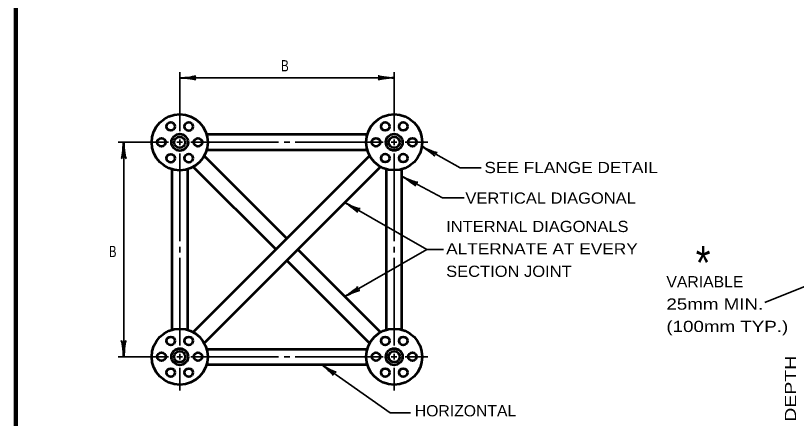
# Model space of a CAD drawing. Extents: x -29 to 827, y -14 to 530.
# Drawn here: x 28.3 to 196.8, y 249.5 to 336.4 of the extents above; entities that cross this region are included whole.
import ezdxf

# ---------------------------------------------------------------- set-up
doc = ezdxf.new("R2010")
doc.units = 0
doc.header["$LTSCALE"] = 0.97
doc.layers.add('1', color=7, linetype='Continuous', lineweight=53)

msp = doc.modelspace()

# ---------------------------------------------------------------- linework, layer by layer
at = {"layer": '1', "lineweight": 35}
for p, q in [((63.7556, 324.1479), (63.7556, 311.4169)), ((110.0276, 324.1479), (110.0276, 311.4279)), ((63.7556, 322.9239), (110.0276, 322.9239)), ((50.4356, 309.0279), (61.3488, 309.0279)), ((51.6596, 309.0279), (51.6596, 262.7559)), ((63.1556, 309.0279), (64.3556, 309.0279)), ((63.7556, 309.6279), (63.7556, 308.4039)), ((66.1488, 309.0279), (69.8036, 309.0279)), ((69.8036, 309.0279), (85.0676, 309.0279)), ((86.2676, 309.0279), (87.4916, 309.0279)), ((88.6916, 309.0279), (103.9796, 309.0279)), ((103.9796, 309.0279), (107.6276, 309.0279)), ((112.4276, 309.0279), (117.2756, 309.0279)), ((63.7556, 306.6169), (63.7556, 302.9799)), ((110.0276, 306.6279), (110.0276, 302.9799)), ((63.7556, 287.6919), (63.7556, 302.9799)), ((110.0276, 302.9799), (110.0276, 287.6919)), ((63.7556, 285.2679), (63.7556, 286.4919)), ((110.0276, 286.4919), (110.0276, 285.2679)), ((117.0596, 285.8919), (120.6836, 285.8919)), ((63.7556, 268.8039), (63.7556, 284.0679)), ((110.0276, 284.0679), (110.0276, 268.8039)), ((207.7316, 281.5678), (190.0196, 274.4878)), ((63.7556, 268.8039), (63.7556, 265.1559)), ((110.0276, 268.8039), (110.0276, 265.1559)), ((50.4356, 262.7559), (61.3556, 262.7559)), ((66.1556, 262.7559), (69.8036, 262.7559)), ((69.8036, 262.7559), (85.0676, 262.7559)), ((86.2676, 262.7559), (87.4916, 262.7559)), ((88.6916, 262.7559), (103.9796, 262.7559)), ((103.9796, 262.7559), (107.6276, 262.7559)), ((112.4276, 262.7559), (117.2756, 262.7559)), ((63.7556, 260.3559), (63.7556, 255.4839)), ((110.0276, 260.3559), (110.0276, 255.4839))]:
    msp.add_line(p, q, dxfattribs=at)
at = {"layer": '1'}
for p, q in [((104.1956, 310.6839), (69.5636, 310.6839)), ((104.1956, 307.3479), (69.5636, 307.3479)), ((104.7236, 306.0759), (66.6836, 268.0359)), ((69.0356, 306.0759), (86.8916, 288.2439)), ((66.6836, 303.7239), (84.5396, 285.8919)), ((107.0756, 303.7239), (69.0356, 265.6839)), ((62.0756, 303.1959), (62.0756, 268.5639)), ((65.4116, 303.1959), (65.4116, 268.5639)), ((108.3476, 268.5639), (108.3476, 303.1959)), ((111.6836, 268.5639), (111.6836, 303.1959)), ((89.2436, 285.8919), (107.0756, 268.0359)), ((86.8916, 283.5399), (104.7236, 265.6839)), ((69.5636, 264.4119), (104.1956, 264.4119)), ((69.5636, 261.0759), (104.1956, 261.0759))]:
    msp.add_line(p, q, dxfattribs=at)
at = {"layer": '1', "lineweight": 158}
msp.add_lwpolyline([(820.0407, 523.2545), (28.3407, 523.1545), (28.4407, -2.8455)], dxfattribs=at)
at = {"layer": '1', "lineweight": 35}
for points in [[(109.4036, 309.0279), (110.0276, 309.0279), (110.6276, 309.0279)], [(110.0276, 309.6279), (110.0276, 309.0279), (110.0276, 308.4039)], [(116.0276, 308.1399), (124.2836, 303.4839), (128.8196, 303.4839)], [(111.8276, 301.6119), (120.4436, 297.0279), (125.1236, 297.0279)], [(99.3716, 296.0199), (117.0596, 285.8919), (99.3716, 275.7399)], [(63.7556, 263.3559), (63.7556, 262.7559), (63.7556, 262.1559)], [(110.0276, 263.3559), (110.0276, 262.7559), (110.0276, 262.1559)], [(63.1556, 262.7559), (63.7556, 262.7559), (64.3556, 262.7559)], [(109.4036, 262.7559), (110.0276, 262.7559), (110.6276, 262.7559)], [(94.3316, 261.0759), (109.1396, 250.6839), (113.5556, 250.6839)]]:
    msp.add_lwpolyline(points, dxfattribs=at)
at = {"layer": '1'}
for centre, radius in [((63.7488, 309.0169), 6.048), ((110.0276, 309.0279), 6.048), ((108.0844, 312.4522), 0.9), ((111.9844, 312.4444), 0.9), ((61.8056, 312.4412), 0.9), ((65.7056, 312.4334), 0.9), ((63.7488, 309.0169), 1.8), ((63.7488, 309.0169), 1.2), ((110.0276, 309.0279), 1.8), ((110.0276, 309.0279), 1.2), ((59.8116, 309.0279), 0.9), ((67.686, 309.0279), 0.9), ((106.0904, 309.0389), 0.9), ((113.9648, 309.0389), 0.9), ((61.8056, 305.5926), 0.9), ((65.7056, 305.6004), 0.9), ((108.0844, 305.6036), 0.9), ((111.9844, 305.6114), 0.9), ((63.7556, 262.7559), 6.048), ((110.0276, 262.7559), 6.048), ((61.8124, 266.1802), 0.9), ((65.7124, 266.1724), 0.9), ((108.0844, 266.1802), 0.9), ((111.9844, 266.1724), 0.9), ((63.7556, 262.7559), 1.8), ((110.0276, 262.7559), 1.8), ((59.8184, 262.7669), 0.9), ((63.7556, 262.7559), 1.2), ((67.6928, 262.7669), 0.9), ((106.0904, 262.7669), 0.9), ((110.0276, 262.7559), 1.2), ((113.9648, 262.7669), 0.9), ((61.8124, 259.3316), 0.9), ((65.7124, 259.3394), 0.9), ((108.0844, 259.3316), 0.9), ((111.9844, 259.3394), 0.9)]:
    msp.add_circle(centre, radius, dxfattribs=at)
at = {"layer": '1', "lineweight": 40}
for centre, major_axis, ratio, start_param, end_param in [((65.1042, 322.6714), (-2.1246, 0.2125), 0.07063, 3.14071475, 5.41810995), ((65.1042, 322.6714), (-2.1246, 0.2125), 0.07063, 3.14071475, 5.41810995), ((65.0687, 323.2615), (-2.16, -0.1889), 0.122415, 0.89635335, 3.14159265), ((65.0687, 323.2615), (-2.16, -0.1889), 0.122415, 0.89635335, 3.14159265), ((108.6961, 322.5931), (2.16, 0.1889), 0.122415, 0.89635335, 3.14159265), ((108.6961, 322.5931), (2.16, 0.1889), 0.122415, 0.89635335, 3.14159265), ((108.6606, 323.1833), (2.1246, -0.2125), 0.07063, 3.14071475, 5.41810995), ((108.6606, 323.1833), (2.1246, -0.2125), 0.07063, 3.14071475, 5.41810995), ((51.3968, 307.6616), (0.2125, 2.1246), 0.07063, 3.14071475, 5.41810995), ((51.3968, 307.6616), (0.2125, 2.1246), 0.07063, 3.14071475, 5.41810995), ((51.987, 307.697), (-0.1889, 2.16), 0.122415, 0.89635335, 3.14159265), ((51.987, 307.697), (-0.1889, 2.16), 0.122415, 0.89635335, 3.14159265), ((117.0906, 307.2522), (-1.7435, 1.2325), 0.07063, 3.14071475, 5.41810995), ((117.0906, 307.2522), (-1.7435, 1.2325), 0.07063, 3.14071475, 5.41810995), ((117.3508, 307.783), (-1.9722, 0.9008), 0.122415, 0.89635335, 3.14159265), ((117.3508, 307.783), (-1.9722, 0.9008), 0.122415, 0.89635335, 3.14159265), ((112.9021, 300.7546), (1.7745, -1.1875), 0.07063, 6.28230741, 8.55970261), ((113.1486, 301.292), (-1.9946, 0.8501), 0.122415, 0.89635335, 3.14159265), ((100.4304, 295.1344), (1.7367, -1.2422), 0.07063, 6.28230741, 8.55970261), ((100.6936, 295.6638), (-1.9672, 0.9118), 0.122415, 0.89635335, 3.14159265), ((100.3607, 276.6824), (-1.7791, -1.2394), 0.122415, 0.89635335, 3.14159265), ((100.6853, 276.1882), (-1.9483, -0.8737), 0.07063, 3.14071475, 5.41810995), ((51.3186, 264.0696), (0.1889, -2.16), 0.122415, 0.89635335, 3.14159265), ((51.9087, 264.1051), (-0.2125, -2.1246), 0.07063, 3.14071475, 5.41810995), ((95.3027, 260.0982), (-1.6167, 1.3948), 0.07063, 3.14071475, 5.41810995), ((95.6129, 260.6016), (-1.8763, 1.0866), 0.122415, 0.89635335, 3.14159265)]:
    msp.add_ellipse(centre, major_axis=major_axis, ratio=ratio, start_param=start_param, end_param=end_param, dxfattribs=at)

# ---------------------------------------------------------------- texts
at = {"layer": '1'}
for s, height, width, p in [('B', 2.419, 0.75, (85.6436, 324.3291)), ('SEE FLANGE DETAIL', 2.419, 1.15, (129.4916, 302.3799)), ('VERTICAL DIAGONAL', 2.419, 1.1, (125.3876, 295.7799)), ('INTERNAL DIAGONALS', 2.419, 1.1, (121.2356, 289.6599)), ('B', 2.419, 0.75, (48.4916, 284.2599)), ('ALTERNATE AT EVERY', 2.419, 1.15, (121.2356, 284.8359)), ('*', 7.2, 0.85, (175.0878, 279.4552)), ('SECTION JOINT', 2.419, 1.1, (121.2356, 279.9879)), ('VARIABLE', 2.419, 1.05, (168.7578, 277.7278)), ('25mm MIN.', 2.419, 1.25, (168.7578, 272.9086)), ('(100mm TYP.)', 2.419, 1.25, (168.7578, 268.0894)), ('HORIZONTAL', 2.419, 1.05, (114.4676, 249.8919))]:
    msp.add_text(s, height=height, dxfattribs=dict(at, width=width)).set_placement(p)
at = {"layer": '1', "width": 1.3}
msp.add_text('D    TOTAL DEPTH', height=2.419, rotation=90, dxfattribs=at).set_placement((196.7396, 226.2958))

doc.saveas('drawing.dxf')
